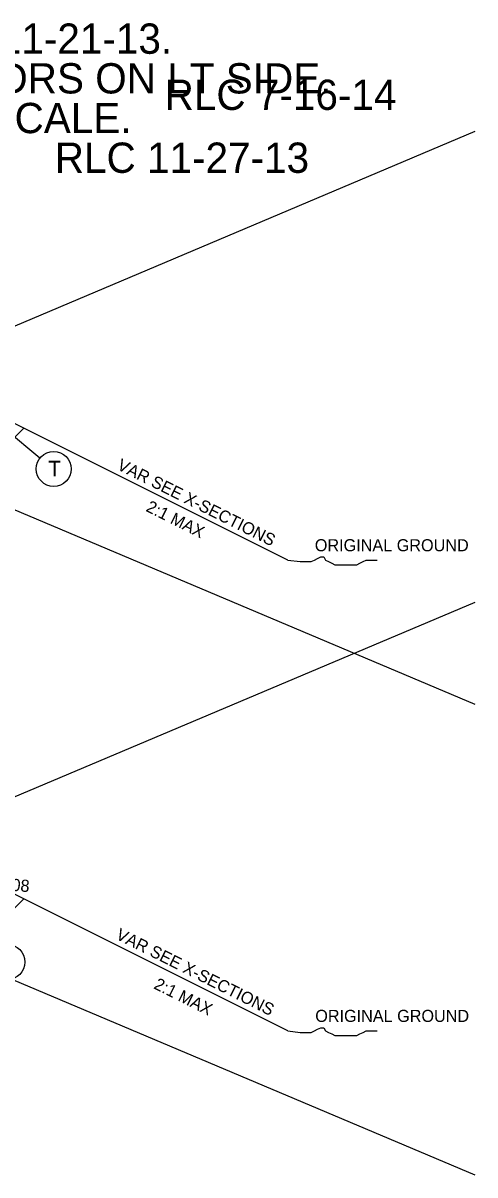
# Model space of a CAD drawing. Extents: x 573732 to 574187, y -53389 to -53257.
# Drawn here: x 574084 to 574121.4, y -53363.5 to -53268.4 of the extents above; entities that cross this region are included whole.
import ezdxf

# ---------------------------------------------------------------- set-up
doc = ezdxf.new("R2010")
doc.units = 0
for name, color, linetype in [('Default', 7, 'Continuous'), ('Typical ID Circle CELL', 7, 'Continuous'), ('Typical Pavement Slope Information CELL', 7, 'Continuous'), ('Typical Shoulder Slope CELL', 7, 'Continuous'), ('Typical Shoulder Slope Information CELL', 7, 'Continuous'), ('Typical Slope Point Local CELL', 7, 'Continuous'), ('Typical Text ID Circle CELL', 7, 'Continuous')]:
    doc.layers.add(name, color=color, linetype=linetype)

msp = doc.modelspace()

# ---------------------------------------------------------------- linework, layer by layer
at = {"layer": 'Default'}
for p, q in [((574009.442, -53277.39), (574121.356, -53324.666)), ((574121.356, -53277.39), (574009.442, -53324.666)), ((574009.442, -53316.258), (574121.356, -53363.534)), ((574121.356, -53316.258), (574009.442, -53363.534))]:
    msp.add_line(p, q, dxfattribs=at)
at = {"layer": 'Typical ID Circle CELL'}
msp.add_line((574085.439, -53304.353), (574082.598, -53301.987), dxfattribs=at)
for centre in [(574086.577, -53305.24), (574082.747, -53345.953)]:
    msp.add_circle(centre, 1.443, dxfattribs=at)
at = {"layer": 'Typical Shoulder Slope CELL'}
for p, q in [((574083.012, -53302.966), (574084.106, -53301.872)), ((574083.012, -53341.835), (574084.106, -53340.74))]:
    msp.add_line(p, q, dxfattribs=at)
at = {"layer": 'Typical Slope Point Local CELL'}
for p, q in [((574105.895, -53312.767), (574083.395, -53301.516)), ((574105.895, -53351.635), (574083.395, -53340.385))]:
    msp.add_line(p, q, dxfattribs=at)
for points in [[(574105.895, -53312.767), (574106.932, -53312.896), (574107.191, -53312.896), (574107.581, -53312.896), (574107.84, -53312.896), (574108.1, -53312.767), (574108.359, -53312.636), (574108.618, -53312.506), (574108.878, -53312.506), (574109.008, -53312.767), (574109.267, -53312.896), (574109.526, -53313.026), (574109.786, -53313.155), (574110.045, -53313.155), (574110.304, -53313.155), (574110.564, -53313.155), (574110.823, -53313.155), (574111.082, -53313.155), (574111.342, -53313.155), (574111.601, -53313.155), (574111.86, -53313.026), (574112.12, -53312.896), (574112.379, -53312.767), (574112.769, -53312.767), (574113.028, -53312.767), (574113.287, -53312.767)], [(574105.895, -53351.635), (574106.932, -53351.764), (574107.191, -53351.764), (574107.581, -53351.764), (574107.84, -53351.764), (574108.1, -53351.635), (574108.359, -53351.505), (574108.618, -53351.375), (574108.878, -53351.375), (574109.008, -53351.635), (574109.267, -53351.764), (574109.526, -53351.894), (574109.786, -53352.024), (574110.045, -53352.024), (574110.304, -53352.024), (574110.564, -53352.024), (574110.823, -53352.024), (574111.082, -53352.024), (574111.342, -53352.024), (574111.601, -53352.024), (574111.86, -53351.894), (574112.12, -53351.764), (574112.379, -53351.635), (574112.769, -53351.635), (574113.028, -53351.635), (574113.287, -53351.635)]]:
    msp.add_lwpolyline(points, dxfattribs=at)

# ---------------------------------------------------------------- texts
at = {"layer": 'Default'}
for s, p in [('THESE TYPICALS WERE SHOWN AT CFI 11-21-13.', (574016.662, -53270.966)), ('TYPICALS MODIFIED TO SHOW 7\'-8" SHLDRS ON LT SIDE.', (574016.662, -53274.243)), ('RLC 7-16-14', (574095.733, -53275.601)), ('TYPICALS MODIFIED TO BE DRAWN TO SCALE.', (574016.662, -53277.52)), ('RLC 11-27-13', (574086.662, -53280.797))]:
    msp.add_text(s, height=2.5, dxfattribs=at).set_placement(p)
at = {"layer": 'Typical Pavement Slope Information CELL'}
for p in [(574108.134, -53312.042), (574108.169, -53350.901)]:
    msp.add_text('ORIGINAL GROUND', height=1, rotation=360, dxfattribs=at).set_placement(p)
at = {"layer": 'Typical Shoulder Slope Information CELL'}
msp.add_text('0.08', height=1, rotation=355.23853, dxfattribs=at).set_placement((574081.944, -53339.97))
at = {"layer": 'Typical Slope Point Local CELL'}
for s, p in [('VAR SEE X-SECTIONS', (574091.731, -53305.241)), ('2:1 MAX', (574094.117, -53308.691)), ('VAR SEE X-SECTIONS', (574091.628, -53344.007)), ('2:1 MAX', (574094.767, -53348.104))]:
    msp.add_text(s, height=1, rotation=333.43495, dxfattribs=at).set_placement(p)
at = {"layer": 'Typical Text ID Circle CELL'}
msp.add_text('T ', height=1.2912, dxfattribs=at).set_placement((574086.117, -53305.86))

doc.saveas('drawing.dxf')
